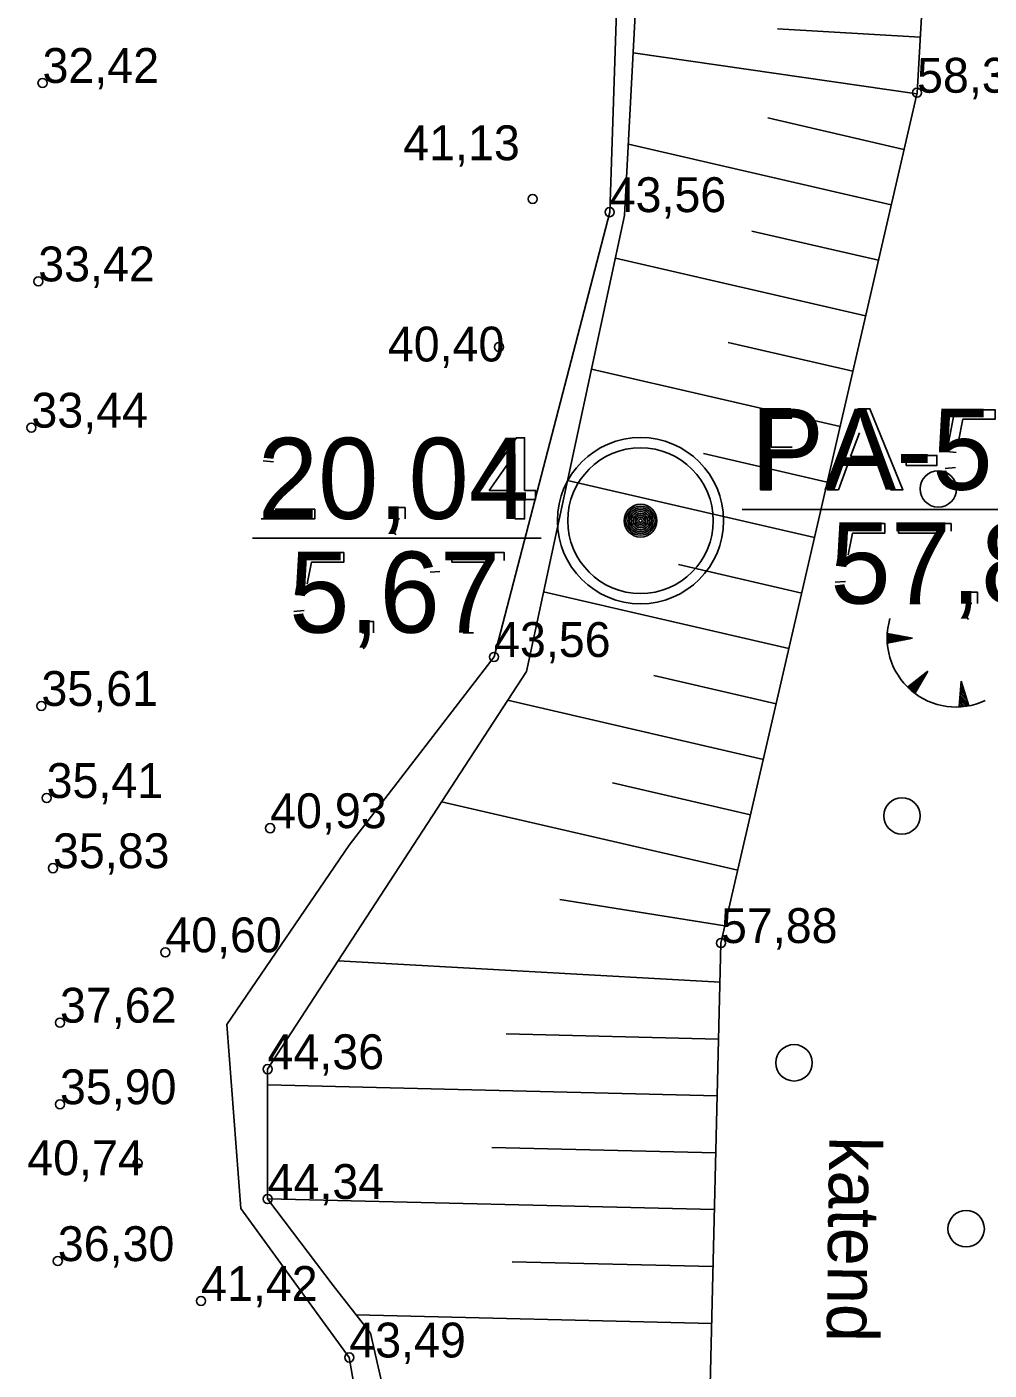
# Model space of a CAD drawing. Extents: x 700746 to 706058, y 6570320 to 6580460.
# Drawn here: x 703265.3 to 703333, y 6576425.7 to 6576520.1 of the extents above; entities that cross this region are included whole.
import ezdxf

# ---------------------------------------------------------------- set-up
doc = ezdxf.new("R2010")
doc.units = 0
for name, color, linetype in [('GEOLPUNKT', 7, 'Continuous'), ('HALJASTUS', 7, 'Continuous'), ('KORGUS-EH2000', 7, 'Continuous'), ('RELJEEF', 7, 'Continuous'), ('VEEKOGU', 7, 'Continuous')]:
    doc.layers.add(name, color=color, linetype=linetype)

msp = doc.modelspace()

# ---------------------------------------------------------------- linework, layer by layer
at = {"layer": 'GEOLPUNKT'}
for p, q in [((703315.605, 6576486.208), (703346.516, 6576486.208)), ((703315.605, 6576486.208), (703346.516, 6576486.208)), ((703281.152, 6576484.209), (703301.462, 6576484.209)), ((703281.152, 6576484.209), (703301.462, 6576484.209))]:
    msp.add_line(p, q, dxfattribs=at)
for points in [[(703316.888, 6576487.606), (703316.888, 6576493.306), (703319.039, 6576493.306)], [(703321.579, 6576487.606), (703323.77, 6576493.306), (703324.586, 6576493.306), (703326.914, 6576487.606), (703326.055, 6576487.606), (703325.395, 6576489.331), (703323.004, 6576489.331), (703322.379, 6576487.606), (703321.579, 6576487.606)], [(703330.664, 6576490.217), (703330.008, 6576490.304), (703330.56, 6576493.232), (703333.393, 6576493.232), (703333.393, 6576492.563), (703331.119, 6576492.563), (703330.813, 6576491.033)], [(703319.102, 6576492.633), (703317.644, 6576492.633), (703317.644, 6576490.595)], [(703299.605, 6576485.559), (703299.605, 6576486.923), (703297.133, 6576486.923), (703297.133, 6576487.566), (703299.731, 6576491.259), (703300.305, 6576491.259), (703300.305, 6576487.566), (703301.074, 6576487.566), (703301.074, 6576486.923), (703300.305, 6576486.923), (703300.305, 6576485.559), (703299.605, 6576485.559)], [(703323.852, 6576491.618), (703323.222, 6576489.944)], [(703323.222, 6576489.944), (703325.158, 6576489.944), (703324.56, 6576491.526)], [(703317.644, 6576490.595), (703319.118, 6576490.595)], [(703282.631, 6576489.56), (703281.91, 6576489.634)], [(703299.605, 6576487.566), (703299.605, 6576490.139), (703297.821, 6576487.566), (703299.605, 6576487.566)], [(703319.106, 6576489.922), (703317.644, 6576489.922), (703317.644, 6576487.606), (703316.888, 6576487.606)], [(703327.15, 6576489.318), (703327.15, 6576490.022), (703329.305, 6576490.022), (703329.305, 6576489.318), (703327.15, 6576489.318)], [(703329.882, 6576489.101), (703330.617, 6576489.162)], [(703285.546, 6576486.232), (703285.546, 6576485.559), (703281.78, 6576485.559)], [(703282.753, 6576486.232), (703285.546, 6576486.232)], [(703291.103, 6576485.559), (703291.103, 6576486.354), (703291.898, 6576486.354), (703291.898, 6576485.559)], [(703291.498, 6576485.559), (703291.103, 6576485.559)], [(703291.251, 6576484.429), (703291.055, 6576484.729)], [(703322.92, 6576482.217), (703322.264, 6576482.304), (703322.816, 6576485.232), (703325.649, 6576485.232), (703325.649, 6576484.563), (703323.375, 6576484.563), (703323.068, 6576483.033)], [(703326.613, 6576484.559), (703326.613, 6576485.232), (703330.302, 6576485.232), (703330.302, 6576484.688)], [(703329.402, 6576484.559), (703326.613, 6576484.559)], [(703284.853, 6576480.17), (703284.197, 6576480.257), (703284.749, 6576483.185), (703287.582, 6576483.185), (703287.582, 6576482.516), (703285.308, 6576482.516), (703285.001, 6576480.986)], [(703295.185, 6576482.511), (703295.185, 6576483.185), (703298.873, 6576483.185), (703298.873, 6576482.64)], [(703294.346, 6576481.86), (703293.651, 6576481.803)], [(703297.974, 6576482.511), (703295.185, 6576482.511)], [(703322.138, 6576481.101), (703322.873, 6576481.162)], [(703331.37, 6576479.606), (703331.37, 6576480.401), (703332.165, 6576480.401), (703332.165, 6576479.606)], [(703284.071, 6576479.053), (703284.806, 6576479.114)], [(703328.129, 6576479.606), (703327.408, 6576479.606)], [(703331.766, 6576479.606), (703331.37, 6576479.606)], [(703288.876, 6576477.559), (703288.876, 6576478.354), (703289.671, 6576478.354), (703289.671, 6576477.559)], [(703331.518, 6576478.477), (703331.323, 6576478.777)], [(703289.272, 6576477.559), (703288.876, 6576477.559)], [(703296.701, 6576477.559), (703295.98, 6576477.559)], [(703289.024, 6576476.429), (703288.829, 6576476.729)]]:
    msp.add_lwpolyline(points, dxfattribs=at)
for radius in [5.842, 5.12, 1.152, 1.025, 0.896, 0.768, 0.64, 0.512, 0.384, 0.256, 0.128]:
    msp.add_circle((703308.455, 6576485.434), radius, dxfattribs=at)
at = {"layer": 'HALJASTUS'}
for centre in [(703329.402, 6576487.668), (703326.843, 6576464.681), (703319.253, 6576447.323), (703331.361, 6576435.66)]:
    msp.add_circle(centre, 1.28, dxfattribs=at)
at = {"layer": 'KORGUS-EH2000'}
for centre in [(703266.393, 6576516.206), (703327.907, 6576515.518), (703300.865, 6576508.052), (703306.287, 6576507.123), (703266.091, 6576502.254), (703298.508, 6576497.639), (703265.61, 6576491.974), (703298.153, 6576475.852), (703266.314, 6576472.41), (703266.68, 6576465.941), (703282.402, 6576463.818), (703267.128, 6576461.005), (703275.029, 6576455.092), (703314.115, 6576455.744), (703267.619, 6576450.147), (703282.222, 6576446.877), (703267.618, 6576444.412), (703273.085, 6576440.262), (703282.226, 6576437.753), (703267.467, 6576433.385), (703277.546, 6576430.586), (703287.969, 6576426.61)]:
    msp.add_circle(centre, 0.32, dxfattribs=at)
at = {"layer": 'RELJEEF'}
for p, q in [((703318.096, 6576520.013), (703328.13, 6576519.419)), ((703327.886, 6576515.427), (703307.941, 6576518.318)), ((703317.401, 6576513.741), (703326.987, 6576511.53)), ((703326.087, 6576507.632), (703307.601, 6576511.897)), ((703316.288, 6576505.788), (703325.188, 6576503.735)), ((703324.289, 6576499.837), (703306.693, 6576503.897)), ((703314.62, 6576497.963), (703323.389, 6576495.939)), ((703322.49, 6576492.042), (703305.006, 6576496.076)), ((703312.877, 6576490.155), (703321.591, 6576488.144)), ((703320.692, 6576484.247), (703303.319, 6576488.255)), ((703311.134, 6576482.347), (703319.792, 6576480.349)), ((703318.893, 6576476.451), (703301.633, 6576480.434)), ((703325.801, 6576477.199), (703326.119, 6576477.454)), ((703325.802, 6576477.097), (703326.223, 6576477.434)), ((703325.803, 6576477.303), (703326.016, 6576477.474)), ((703325.805, 6576476.997), (703326.326, 6576477.414)), ((703325.807, 6576477.408), (703325.913, 6576477.494)), ((703325.809, 6576476.898), (703326.429, 6576477.394)), ((703327.594, 6576477.169), (703325.813, 6576477.513)), ((703327.594, 6576477.169), (703325.814, 6576476.82)), ((703325.847, 6576476.826), (703326.532, 6576477.374)), ((703326.017, 6576476.859), (703326.635, 6576477.354)), ((703326.187, 6576476.893), (703326.738, 6576477.334)), ((703326.356, 6576476.926), (703326.841, 6576477.314)), ((703326.526, 6576476.959), (703326.944, 6576477.294)), ((703326.695, 6576476.993), (703327.048, 6576477.274)), ((703326.865, 6576477.026), (703327.151, 6576477.255)), ((703327.035, 6576477.059), (703327.254, 6576477.235)), ((703327.204, 6576477.092), (703327.357, 6576477.215)), ((703327.374, 6576477.126), (703327.46, 6576477.195)), ((703309.391, 6576474.539), (703317.994, 6576472.554)), ((703328.656, 6576474.864), (703327.234, 6576473.738)), ((703328.656, 6576474.864), (703327.761, 6576473.287)), ((703327.777, 6576473.316), (703327.808, 6576474.193)), ((703327.863, 6576473.467), (703327.891, 6576474.258)), ((703327.948, 6576473.617), (703327.973, 6576474.323)), ((703328.033, 6576473.767), (703328.055, 6576474.388)), ((703328.119, 6576473.918), (703328.138, 6576474.454)), ((703328.204, 6576474.068), (703328.22, 6576474.519)), ((703328.289, 6576474.218), (703328.302, 6576474.584)), ((703328.375, 6576474.369), (703328.385, 6576474.649)), ((703328.46, 6576474.519), (703328.467, 6576474.715)), ((703328.545, 6576474.669), (703328.549, 6576474.78)), ((703327.309, 6576473.665), (703327.314, 6576473.801)), ((703327.387, 6576473.593), (703327.396, 6576473.867)), ((703327.465, 6576473.525), (703327.479, 6576473.932)), ((703327.542, 6576473.459), (703327.561, 6576473.997)), ((703327.62, 6576473.395), (703327.644, 6576474.062)), ((703327.698, 6576473.334), (703327.726, 6576474.128)), ((703330.999, 6576474.147), (703330.864, 6576472.339)), ((703331.436, 6576472.782), (703330.934, 6576473.278)), ((703331.384, 6576472.946), (703330.942, 6576473.383)), ((703331.331, 6576473.111), (703330.95, 6576473.488)), ((703331.278, 6576473.276), (703330.958, 6576473.593)), ((703331.226, 6576473.44), (703330.965, 6576473.697)), ((703331.173, 6576473.605), (703330.973, 6576473.802)), ((703331.12, 6576473.769), (703330.981, 6576473.907)), ((703331.068, 6576473.934), (703330.989, 6576474.012)), ((703330.999, 6576474.147), (703331.552, 6576472.42)), ((703317.095, 6576468.656), (703299.102, 6576472.807)), ((703330.968, 6576472.345), (703330.871, 6576472.44)), ((703331.074, 6576472.353), (703330.879, 6576472.545)), ((703331.177, 6576472.363), (703330.887, 6576472.65)), ((703331.278, 6576472.376), (703330.895, 6576472.755)), ((703331.377, 6576472.39), (703330.903, 6576472.859)), ((703331.475, 6576472.406), (703330.911, 6576472.964)), ((703331.542, 6576472.452), (703330.918, 6576473.069)), ((703331.489, 6576472.617), (703330.926, 6576473.174)), ((703306.487, 6576466.999), (703316.195, 6576464.759)), ((703315.296, 6576460.861), (703294.455, 6576465.669)), ((703302.789, 6576458.802), (703314.397, 6576456.963)), ((703314.049, 6576452.996), (703287.184, 6576454.499)), ((703299.013, 6576449.36), (703313.952, 6576448.997)), ((703313.855, 6576444.999), (703282.222, 6576445.766)), ((703297.991, 6576441.382), (703313.758, 6576441)), ((703313.661, 6576437.001), (703282.226, 6576437.764)), ((703299.436, 6576433.345), (703313.564, 6576433.002)), ((703313.466, 6576429.003), (703288.448, 6576429.61))]:
    msp.add_line(p, q, dxfattribs=at)
for points in [[(703290.628, 6576796.525), (703294.184, 6576752.737), (703301.261, 6576735.921), (703310.061, 6576699.515), (703308, 6576689.73), (703309.22, 6576677.546), (703319.192, 6576654.755), (703329.818, 6576561.839), (703330.054, 6576553.021), (703327.907, 6576515.518), (703314.115, 6576455.744), (703313.172, 6576416.874), (703317.14, 6576393.59), (703321.814, 6576369.95), (703317.506, 6576328.08), (703300.909, 6576256.13), (703281.534, 6576125.339), (703279.972, 6576118.459), (703265.553, 6576092.544), (703268.129, 6576079.379)], [(703310.115, 6576559.44), (703307.336, 6576506.877), (703300.426, 6576474.841), (703282.222, 6576446.877), (703282.226, 6576437.753), (703286.833, 6576431.677), (703289.459, 6576428.318), (703294.011, 6576408.353), (703296.876, 6576402.151), (703300.914, 6576385.052), (703303.377, 6576364.564), (703303.353, 6576342.853)]]:
    msp.add_lwpolyline(points, dxfattribs=at)
msp.add_arc((703330.645, 6576477.177), 4.844, 163.42341, 295.17451, dxfattribs=at)
at = {"layer": 'VEEKOGU'}
msp.add_lwpolyline([(703301.759, 6576342.755), (703301.784, 6576365.916), (703299.224, 6576387.468), (703296.182, 6576401.818), (703291.43, 6576406.878), (703287.969, 6576426.61), (703280.351, 6576437.094), (703279.364, 6576450.014), (703287.965, 6576462.626), (703298.153, 6576475.852), (703306.287, 6576507.123), (703308.055, 6576560.199)], dxfattribs=at)
msp.add_lwpolyline([(703301.759, 6576342.755), (703301.784, 6576365.916), (703299.224, 6576387.468), (703296.182, 6576401.818), (703291.43, 6576406.878), (703287.969, 6576426.61), (703280.351, 6576437.094), (703279.364, 6576450.014), (703287.965, 6576462.626), (703298.153, 6576475.852), (703306.287, 6576507.123), (703308.055, 6576560.199)], dxfattribs=at)

# ---------------------------------------------------------------- texts
at = {"layer": 'GEOLPUNKT'}
for s, p in [('PA-5110', (703316.275, 6576487.606)), ('20,04', (703281.541, 6576485.559)), ('57,89*', (703321.808, 6576479.606)), ('5,67', (703283.741, 6576477.559))]:
    msp.add_text(s, height=5.7, dxfattribs=at).set_placement(p)
at = {"layer": 'KORGUS-EH2000'}
for s, p in [('32,42 ', (703266.393, 6576516.206)), ('58,31 ', (703327.907, 6576515.518)), ('41,13 ', (703291.767, 6576510.773)), ('43,56 ', (703306.287, 6576507.123)), ('33,42 ', (703266.091, 6576502.254)), ('40,40 ', (703290.68, 6576496.623)), ('33,44 ', (703265.61, 6576491.974)), ('43,56 ', (703298.153, 6576475.852)), ('35,61 ', (703266.314, 6576472.41)), ('35,41 ', (703266.68, 6576465.941)), ('40,93 ', (703282.402, 6576463.818)), ('35,83 ', (703267.128, 6576461.005)), ('57,88 ', (703314.115, 6576455.744)), ('40,60 ', (703275.029, 6576455.092)), ('37,62 ', (703267.619, 6576450.147)), ('44,36 ', (703282.222, 6576446.877)), ('35,90 ', (703267.618, 6576444.412)), ('40,74 ', (703265.317, 6576439.425)), ('44,34 ', (703282.226, 6576437.753)), ('36,30 ', (703267.467, 6576433.385)), ('41,42 ', (703277.546, 6576430.586)), ('43,49 ', (703287.969, 6576426.61))]:
    msp.add_text(s, height=2.45, dxfattribs=at).set_placement(p)
at = {"layer": 'RELJEEF'}
msp.add_text('katend', height=3.6, rotation=269.22913, dxfattribs=at).set_placement((703321.745, 6576442.171))

doc.saveas('drawing.dxf')
